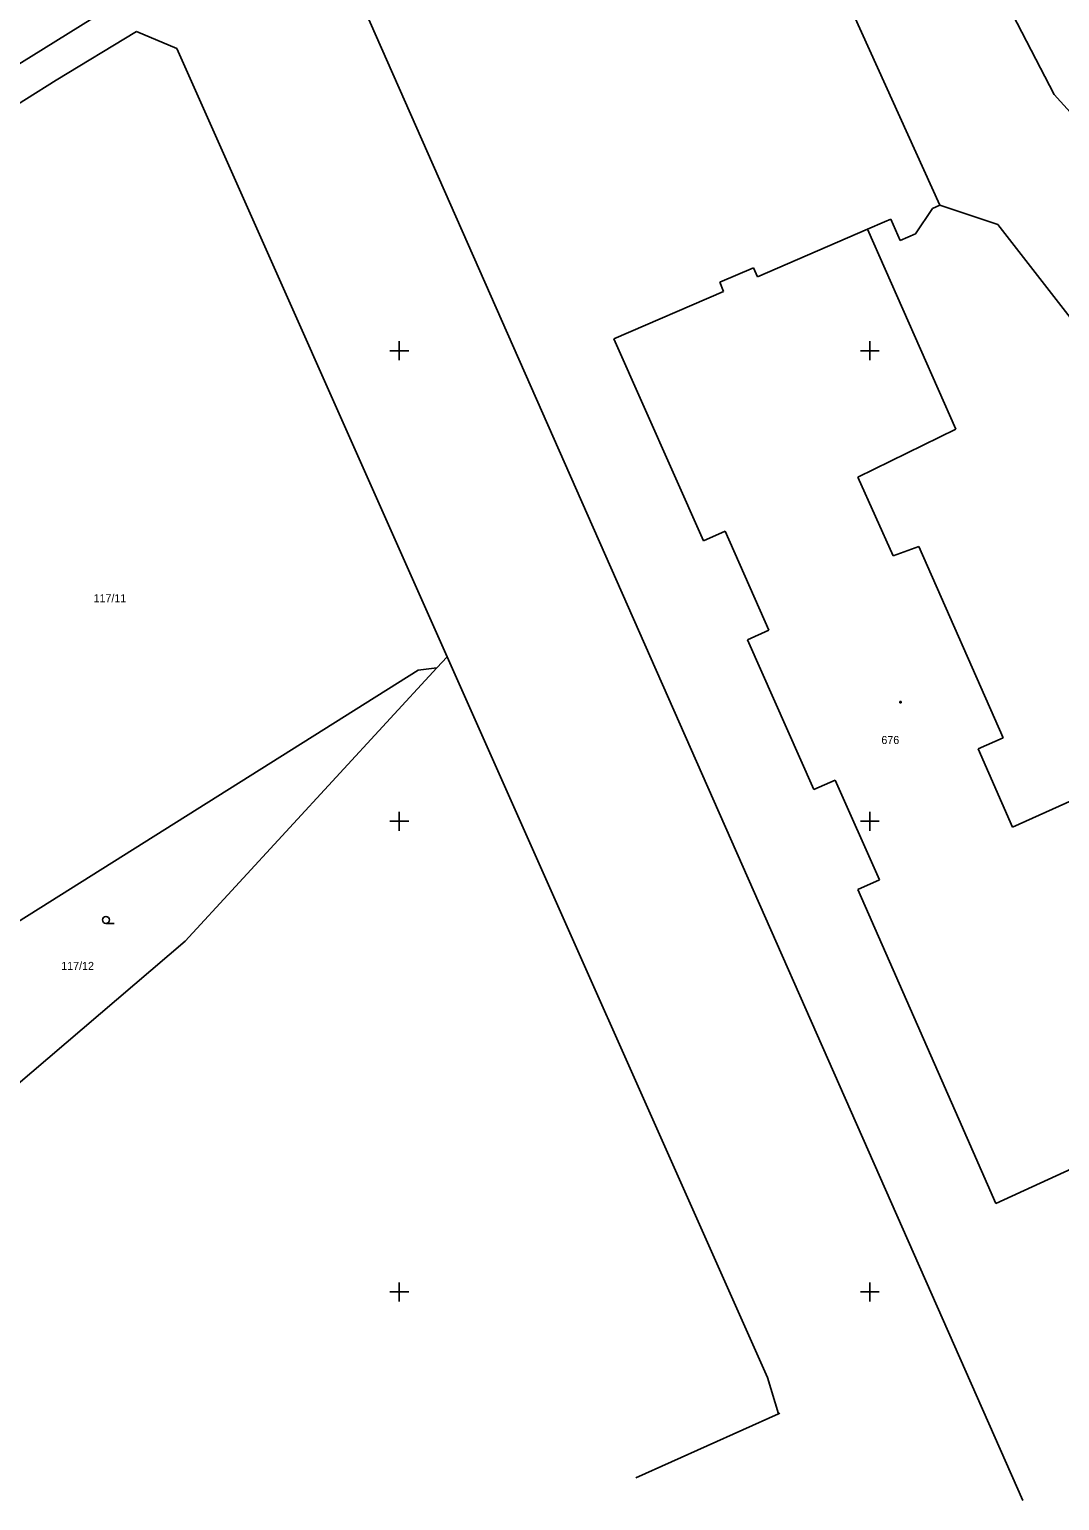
# Model space of a CAD drawing. Extents: x -492379 to -491966, y -1126153 to -1125860.
# Drawn here: x -492233.6 to -492167.9, y -1126153.3 to -1126059.5 of the extents above; entities that cross this region are included whole.
import ezdxf

# ---------------------------------------------------------------- set-up
doc = ezdxf.new("R2010")
doc.units = 0
doc.layers.add('katastrální mapa', color=7, linetype='Continuous')
doc.layers.add('síť', color=7, linetype='Continuous')

msp = doc.modelspace()

# ---------------------------------------------------------------- linework, layer by layer
at = {"layer": 'katastrální mapa'}
for p, q in [((-492182.01, -1126037.16), (-492168.25, -1126063.67)), ((-492187.99, -1126043.23), (-492175.55, -1126070.73)), ((-492213.56, -1126055.22), (-492170.25, -1126153.3)), ((-492282.7, -1126091.84), (-492226.15, -1126056.69)), ((-492231.88, -1126062.75), (-492226.75, -1126059.64)), ((-492226.75, -1126059.64), (-492224.18, -1126060.74)), ((-492224.18, -1126060.74), (-492206.95, -1126099.51)), ((-492253.63, -1126076.45), (-492231.88, -1126062.75)), ((-492168.25, -1126063.67), (-492150.02, -1126083.86)), ((-492176.01, -1126070.93), (-492175.55, -1126070.73)), ((-492175.55, -1126070.73), (-492171.84, -1126071.95)), ((-492179.07, -1126071.79), (-492178.66, -1126071.61)), ((-492178.66, -1126071.61), (-492178.07, -1126072.98)), ((-492177.1, -1126072.54), (-492176.01, -1126070.93)), ((-492187.17, -1126075.29), (-492180.16, -1126072.26)), ((-492180.16, -1126072.26), (-492179.07, -1126071.79)), ((-492180.16, -1126072.26), (-492174.52, -1126084.99)), ((-492178.07, -1126072.98), (-492177.1, -1126072.54)), ((-492171.84, -1126071.95), (-492166.94, -1126078.26)), ((-492189.57, -1126075.63), (-492187.42, -1126074.71)), ((-492187.42, -1126074.71), (-492187.17, -1126075.29)), ((-492196.32, -1126079.24), (-492189.33, -1126076.22)), ((-492189.57, -1126075.63), (-492189.33, -1126076.22)), ((-492196.32, -1126079.24), (-492190.6, -1126092.11)), ((-492180.76, -1126088.05), (-492174.52, -1126084.99)), ((-492180.76, -1126088.05), (-492178.51, -1126093.07)), ((-492190.6, -1126092.11), (-492189.23, -1126091.5)), ((-492189.23, -1126091.5), (-492186.44, -1126097.81)), ((-492178.51, -1126093.07), (-492176.89, -1126092.47)), ((-492176.89, -1126092.47), (-492171.5, -1126104.67)), ((-492187.81, -1126098.42), (-492186.44, -1126097.81)), ((-492187.81, -1126098.42), (-492183.58, -1126107.98)), ((-492207.6, -1126100.22), (-492206.95, -1126099.51)), ((-492206.95, -1126099.51), (-492186.53, -1126145.46)), ((-492240.49, -1126120.29), (-492208.8, -1126100.37)), ((-492223.65, -1126117.64), (-492207.6, -1126100.22)), ((-492208.8, -1126100.37), (-492207.6, -1126100.22)), ((-492178.1, -1126102.36), (-492178.01, -1126102.36)), ((-492178.1, -1126102.45), (-492178.1, -1126102.36)), ((-492178.01, -1126102.45), (-492178.1, -1126102.45)), ((-492178.01, -1126102.36), (-492178.01, -1126102.45)), ((-492170.91, -1126110.38), (-492155.53, -1126103.45)), ((-492173.11, -1126105.37), (-492171.5, -1126104.67)), ((-492173.11, -1126105.37), (-492170.91, -1126110.38)), ((-492183.58, -1126107.98), (-492182.21, -1126107.38)), ((-492182.21, -1126107.38), (-492179.39, -1126113.73)), ((-492180.77, -1126114.34), (-492179.39, -1126113.73)), ((-492180.77, -1126114.34), (-492174.34, -1126128.99)), ((-492228.7, -1126116.51), (-492228.17, -1126116.51)), ((-492235.63, -1126127.85), (-492223.65, -1126117.64)), ((-492174.34, -1126128.99), (-492171.98, -1126134.37)), ((-492171.98, -1126134.37), (-492165.27, -1126131.28)), ((-492186.53, -1126145.46), (-492185.83, -1126147.76)), ((-492194.92, -1126151.84), (-492185.83, -1126147.76)), ((-492185.83, -1126147.76), (-492185.75, -1126147.72))]:
    msp.add_line(p, q, dxfattribs=at)
msp.add_circle((-492228.7, -1126116.285), 0.225, dxfattribs=at)
at = {"layer": 'síť'}
for p, q in [((-492210.6, -1126080), (-492209.4, -1126080)), ((-492210, -1126079.4), (-492210, -1126080.6)), ((-492180.6, -1126080), (-492179.4, -1126080)), ((-492180, -1126079.4), (-492180, -1126080.6)), ((-492210.6, -1126110), (-492209.4, -1126110)), ((-492210, -1126109.4), (-492210, -1126110.6)), ((-492180.6, -1126110), (-492179.4, -1126110)), ((-492180, -1126109.4), (-492180, -1126110.6)), ((-492210.6, -1126140), (-492209.4, -1126140)), ((-492210, -1126139.4), (-492210, -1126140.6)), ((-492180.6, -1126140), (-492179.4, -1126140)), ((-492180, -1126139.4), (-492180, -1126140.6))]:
    msp.add_line(p, q, dxfattribs=at)

# ---------------------------------------------------------------- texts
at = {"layer": 'katastrální mapa'}
for s, p in [('117/11', (-492229.49, -1126096.03)), ('676', (-492179.27, -1126105.07)), ('117/12', (-492231.55, -1126119.47))]:
    msp.add_text(s, height=0.51, dxfattribs=at).set_placement(p)

doc.saveas('drawing.dxf')
